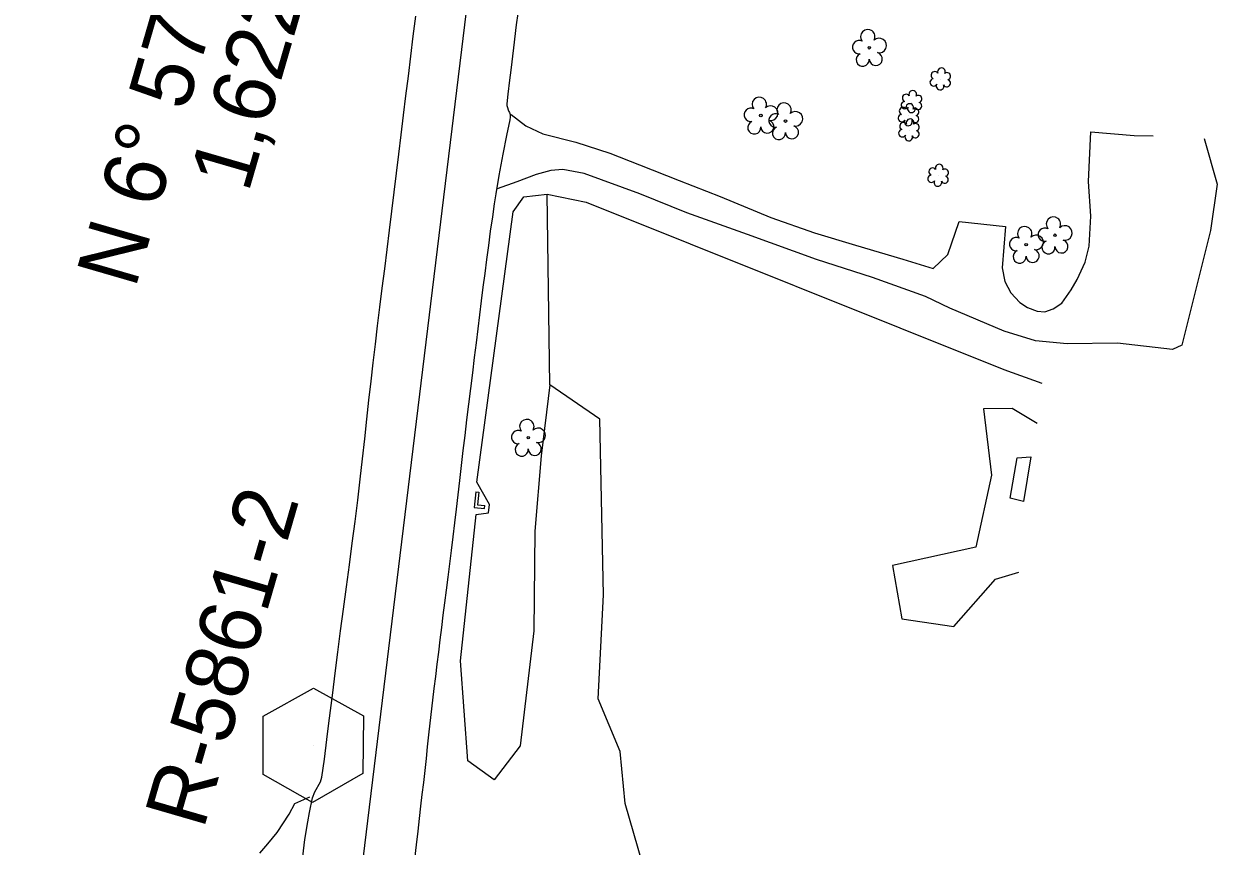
# Model space of a CAD drawing. Extents: x 479429 to 482809, y 488118 to 492379.
# Drawn here: x 481201.3 to 481510.2, y 490268.7 to 490481.6 of the extents above; entities that cross this region are included whole.
import ezdxf

# ---------------------------------------------------------------- set-up
doc = ezdxf.new("R2010")
doc.units = 0
for name, color, linetype in [('CTL Primary Horizontal and Vertical CELL', 7, 'Continuous'), ('CTL Primary Horizontal and Vertical Text', 7, 'Continuous'), ('Exist Horizontal Alignment', 7, 'Continuous'), ('Exist Horizontal Alignment Direction Label', 7, 'Continuous'), ('Exist Other Culture Area Outline', 7, 'Continuous'), ('Exist Roads EOP', 7, 'Continuous'), ('Exist Roads Soil', 7, 'Continuous'), ('Exist Structure Minor Head and End Wall', 7, 'Continuous'), ('Exist Vegetation Hedge Row', 7, 'Continuous'), ('Exist Vegetation Shrub CELL', 7, 'Continuous'), ('Exist Vegetation Tree CELL', 7, 'Continuous'), ('Exist Vegetation Woods Line', 7, 'Continuous')]:
    doc.layers.add(name, color=color, linetype=linetype)

msp = doc.modelspace()

# ---------------------------------------------------------------- linework, layer by layer
at = {"layer": 'CTL Primary Horizontal and Vertical CELL'}
msp.add_line((481276.2, 490294.82), (481276.2, 490294.82), dxfattribs=at)
msp.add_lwpolyline([(481263.27, 490302.31), (481276.27, 490309.56), (481289.27, 490302.41), (481289.07, 490287.51), (481276.07, 490279.96), (481263.27, 490287.21)], close=True, dxfattribs=at)
at = {"layer": 'Exist Horizontal Alignment'}
msp.add_line((481201.31, 489545.89), (481397.95, 491156.7), dxfattribs=at)
at = {"layer": 'Exist Other Culture Area Outline'}
msp.add_lwpolyline([(481462.01, 490369.53), (481460.14, 490357.91), (481456.62, 490358.76), (481458.46, 490369.26), (481462.01, 490369.53)], dxfattribs=at)
at = {"layer": 'Exist Roads EOP'}
for points in [[(481273.37, 490264.51), (481274.03, 490270.38), (481274.8, 490274.93), (481275.25, 490277.39), (481276.03, 490281.18), (481276.68, 490282.73), (481278.07, 490285.35), (481278.31, 490285.97), (481278.46, 490286.53), (481279.11, 490291.18), (481279.77, 490296.33), (481280.21, 490299.8), (481280.72, 490303.81), (481281.28, 490308.38), (481281.92, 490313.5), (481282.6, 490318.93), (481283.31, 490324.46), (481284.05, 490330.08), (481284.81, 490335.79), (481285.58, 490341.51), (481286.32, 490347.16), (481287.04, 490352.75), (481287.73, 490358.27), (481288.38, 490363.7), (481289, 490369), (481289.58, 490374.17), (481290.12, 490379.21), (481290.64, 490384.16), (481291.19, 490389.05), (481291.74, 490393.87), (481292.31, 490398.64), (481292.9, 490403.42), (481293.5, 490408.26), (481294.1, 490413.18), (481294.72, 490418.17), (481295.34, 490423.18), (481295.96, 490428.16), (481296.56, 490433.1), (481297.16, 490438.01), (481297.75, 490442.93), (481298.36, 490447.89), (481298.97, 490452.89), (481299.59, 490457.93), (481300.22, 490463), (481300.85, 490468.11), (481301.49, 490473.25), (481302.13, 490478.41), (481302.77, 490483.61)], [(481329.16, 490484.34), (481328.79, 490481.35), (481328.05, 490475.43), (481327.35, 490469.63), (481327.04, 490467.03), (481326.61, 490463.45), (481326.33, 490460.91), (481326.34, 490460.65), (481326.36, 490460.44), (481326.5, 490459.93), (481326.71, 490459.32), (481326.9, 490458.9), (481327.04, 490458.67), (481327.15, 490458.36), (481327.19, 490458.16), (481327.22, 490457.93), (481327.23, 490457.42), (481327.16, 490456.79), (481326.29, 490452.73), (481325.34, 490447.88), (481324.26, 490442.35), (481323.49, 490437.59), (481323.1, 490434.99), (481322.61, 490431.62), (481322.07, 490427.89), (481321.56, 490424.21), (481321.07, 490420.57), (481320.61, 490416.99), (481320.16, 490413.42), (481319.71, 490409.85), (481319.27, 490406.27), (481318.84, 490402.68), (481318.4, 490399.01), (481317.93, 490395.21), (481317.45, 490391.28), (481316.95, 490387.21), (481316.44, 490383.1), (481315.94, 490379.04), (481315.46, 490375.04), (481314.99, 490371.09), (481314.54, 490367.21), (481314.09, 490363.39), (481313.65, 490359.65), (481313.23, 490355.98), (481312.8, 490352.37), (481312.37, 490348.79), (481311.94, 490345.25), (481311.5, 490341.75), (481311.06, 490338.31), (481310.63, 490334.95), (481310.22, 490331.66), (481309.81, 490328.46), (481309.41, 490325.29), (481309.01, 490322.12), (481308.62, 490318.94), (481308.23, 490315.76), (481307.85, 490312.6), (481307.48, 490309.5), (481307.12, 490306.45), (481306.44, 490300.49), (481306.1, 490297.48), (481305.76, 490294.43), (481305.42, 490291.34), (481305.08, 490288.24), (481304.73, 490285.15), (481304.38, 490282.07), (481304.03, 490279), (481303.66, 490275.85), (481303.27, 490272.51), (481302.86, 490268.99), (481302.43, 490265.28)]]:
    msp.add_lwpolyline(points, dxfattribs=at)
at = {"layer": 'Exist Roads Soil'}
for points in [[(481327.51, 490458.11), (481331.29, 490455.24), (481335.67, 490453.17), (481344.23, 490451.01), (481353, 490448.09), (481360.69, 490445.14), (481370.93, 490441.08), (481381.59, 490436.9), (481394.68, 490431.47), (481406.02, 490427.49), (481416.62, 490424.33), (481428.89, 490420.66), (481436.72, 490418.27), (481440.55, 490421.92), (481443.47, 490430.42), (481455.44, 490429.1), (481454.57, 490418.43), (481455.3, 490414.9), (481456.86, 490411.97), (481459.13, 490409.48), (481461.12, 490408.13), (481463.64, 490407.25), (481465.63, 490407.02), (481467.8, 490407.79), (481470, 490409.32), (481472.47, 490412.7), (481474, 490415.45), (481476.09, 490419.89), (481477.08, 490424.08), (481477.56, 490431.82), (481476.97, 490440.78), (481477.5, 490453.68), (481488.75, 490452.73), (481493.67, 490452.6)], [(481506.89, 490451.91), (481510.24, 490440.06), (481508.48, 490428.08), (481501.06, 490398.42), (481498.72, 490397.25), (481484.43, 490398.92), (481471.41, 490398.74), (481463.22, 490399.51), (481455.09, 490402.02), (481441.03, 490408.02), (481434.75, 490411.02), (481421.03, 490415.89), (481406.48, 490420.61), (481388.65, 490427.04), (481372.96, 490432.66), (481360.8, 490437.59), (481346.39, 490442.84), (481340.87, 490443.86), (481337.73, 490443.63), (481333.95, 490442.59), (481328.94, 490440.73), (481323.87, 490438.9)], [(481262.36, 490266.86), (481264.47, 490269.3), (481266.85, 490272.2), (481269.98, 490276.95), (481271.49, 490279.73), (481275.3, 490281.45)]]:
    msp.add_lwpolyline(points, dxfattribs=at)
at = {"layer": 'Exist Structure Minor Head and End Wall'}
for p, q in [((481318.32, 490360.41), (481319.06, 490360.34)), ((481320.6, 490356.12), (481320.67, 490356.86))]:
    msp.add_line(p, q, dxfattribs=at)
for points in [[(481318.32, 490360.41), (481317.93, 490356.34), (481320.6, 490356.12)], [(481319.06, 490360.34), (481318.75, 490357.02), (481320.67, 490356.86)]]:
    msp.add_lwpolyline(points, dxfattribs=at)
at = {"layer": 'Exist Vegetation Hedge Row'}
msp.add_lwpolyline([(481337.45, 490388.16), (481335.27, 490369.72), (481333.58, 490350.26), (481333.32, 490324.41), (481329.78, 490294.62), (481323.06, 490285.85), (481316.25, 490290.78), (481314.34, 490316.65), (481318.44, 490354.56), (481321.57, 490354.98), (481321.87, 490357.17), (481318.62, 490362.95), (481328.02, 490432.9), (481330.71, 490436.79), (481336.76, 490437.47)], dxfattribs=at)
at = {"layer": 'Exist Vegetation Shrub CELL'}
for p, q in [((481438.64, 490467.18), (481438.64, 490467.18)), ((481431.2, 490461.3), (481431.2, 490461.3)), ((481430.41, 490457.9), (481430.41, 490457.9)), ((481430.53, 490453.98), (481430.53, 490453.98)), ((481438.07, 490442.22), (481438.07, 490442.22))]:
    msp.add_line(p, q, dxfattribs=at)
for centre, radius, start, end in [((481436.84, 490466.47), 0.955, 95.1099, 327.9534), ((481437.16, 490468.3), 0.968, 35.8908, 245.4216), ((481438.87, 490469.22), 0.99, 334.8391, 200.4717), ((481440.31, 490468.05), 0.929, 284.4567, 126.0861), ((481431.43, 490463.34), 0.99, 334.8391, 200.4717), ((481438.51, 490465.49), 0.984, 151.2797, 21.387), ((481440.28, 490466.25), 0.937, 204.9913, 73.4601), ((481429.4, 490460.59), 0.955, 95.1099, 327.9534), ((481429.72, 490462.42), 0.968, 35.8908, 245.4216), ((481432.84, 490460.37), 0.937, 204.9913, 73.4601), ((481432.88, 490462.17), 0.929, 284.4567, 126.0861), ((481428.61, 490457.19), 0.955, 95.1099, 327.9534), ((481428.92, 490459.03), 0.968, 35.8908, 245.4216), ((481430.64, 490459.94), 0.99, 334.8391, 200.4717), ((481431.08, 490459.61), 0.984, 151.2797, 21.387), ((481432.08, 490458.77), 0.929, 284.4567, 126.0861), ((481429.05, 490455.11), 0.968, 35.8908, 245.4216), ((481430.28, 490456.22), 0.984, 151.2797, 21.387), ((481430.76, 490456.02), 0.99, 334.8391, 200.4717), ((481432.04, 490456.97), 0.937, 204.9913, 73.4601), ((481432.2, 490454.85), 0.929, 284.4567, 126.0861), ((481428.73, 490453.28), 0.955, 95.1099, 327.9534), ((481430.4, 490452.3), 0.984, 151.2797, 21.387), ((481432.17, 490453.05), 0.937, 204.9913, 73.4601), ((481436.58, 490443.34), 0.968, 35.8908, 245.4216), ((481438.29, 490444.26), 0.99, 334.8391, 200.4717), ((481439.74, 490443.08), 0.929, 284.4567, 126.0861), ((481436.27, 490441.51), 0.955, 95.1099, 327.9534), ((481437.94, 490440.53), 0.984, 151.2797, 21.387), ((481439.7, 490441.29), 0.937, 204.9913, 73.4601)]:
    msp.add_arc(centre, radius, start, end, dxfattribs=at)
at = {"layer": 'Exist Vegetation Tree CELL'}
for p, q in [((481420.18, 490475.43), (481420.18, 490475.43)), ((481392.1, 490457.89), (481392.1, 490457.89)), ((481398.49, 490456.44), (481398.49, 490456.44)), ((481460.81, 490424.43), (481460.81, 490424.43)), ((481468.26, 490426.88), (481468.26, 490426.88)), ((481331.9, 490374.46), (481331.9, 490374.46))]:
    msp.add_line(p, q, dxfattribs=at)
for centre in [(481420.18, 490475.43), (481392.1, 490457.89), (481398.49, 490456.44), (481468.26, 490426.88), (481460.81, 490424.43), (481331.9, 490374.46)]:
    msp.add_circle(centre, 0.326, dxfattribs=at)
for centre, radius, start, end in [((481419.8, 490478.3), 1.86, 330.1651, 219.7134), ((481417.58, 490475.58), 1.73, 62.6636, 279.3457), ((481422.73, 490476.01), 1.9, 257.1011, 134.1999), ((481418.48, 490472.31), 1.69, 111.5671, 6.231), ((481421.86, 490472.53), 1.7, 181.2822, 74.56), ((481391.71, 490460.76), 1.86, 330.1651, 219.7134), ((481398.1, 490459.32), 1.86, 330.1651, 219.7134), ((481389.49, 490458.04), 1.73, 62.6636, 279.3457), ((481394.65, 490458.48), 1.9, 257.1011, 134.1999), ((481395.88, 490456.6), 1.73, 62.6636, 279.3457), ((481401.04, 490457.03), 1.9, 257.1011, 134.1999), ((481390.39, 490454.77), 1.69, 111.5671, 6.231), ((481393.77, 490454.99), 1.7, 181.2822, 74.56), ((481400.16, 490453.54), 1.7, 181.2822, 74.56), ((481396.78, 490453.32), 1.69, 111.5671, 6.231), ((481467.87, 490429.75), 1.86, 330.1651, 219.7134), ((481460.42, 490427.3), 1.86, 330.1651, 219.7134), ((481465.65, 490427.03), 1.73, 62.6636, 279.3457), ((481470.81, 490427.46), 1.9, 257.1011, 134.1999), ((481458.2, 490424.58), 1.73, 62.6636, 279.3457), ((481463.35, 490425.02), 1.9, 257.1011, 134.1999), ((481466.56, 490423.76), 1.69, 111.5671, 6.231), ((481469.93, 490423.98), 1.7, 181.2822, 74.56), ((481459.1, 490421.31), 1.69, 111.5671, 6.231), ((481462.48, 490421.53), 1.7, 181.2822, 74.56), ((481331.52, 490377.33), 1.86, 330.1651, 219.7134), ((481329.3, 490374.61), 1.73, 62.6636, 279.3457), ((481334.45, 490375.05), 1.9, 257.1011, 134.1999), ((481330.2, 490371.34), 1.69, 111.5671, 6.231), ((481333.58, 490371.56), 1.7, 181.2822, 74.56)]:
    msp.add_arc(centre, radius, start, end, dxfattribs=at)
at = {"layer": 'Exist Vegetation Woods Line'}
for points in [[(481336.76, 490437.47), (481346.91, 490435.42), (481455.03, 490392.14), (481464.88, 490388.54)], [(481355.7, 490293.17), (481349.96, 490306.84), (481351.33, 490333.74), (481350.46, 490379.28), (481337.45, 490388.16), (481336.76, 490437.47)], [(481463.61, 490378.09), (481457.2, 490382.04), (481449.71, 490381.96), (481451.83, 490364.78), (481447.8, 490346.08), (481426.19, 490341.39), (481428.58, 490327.58), (481442.09, 490325.55), (481452.82, 490337.85), (481458.91, 490339.62)], [(481427.35, 490081.24), (481394.6, 490076.17), (481381.34, 490139.35), (481356.08, 490180.77), (481357.25, 490231.7), (481366.21, 490244.77), (481361.43, 490264.2), (481356.94, 490279.7), (481355.7, 490293.17)]]:
    msp.add_lwpolyline(points, dxfattribs=at)

# ---------------------------------------------------------------- texts
at = {"layer": 'CTL Primary Horizontal and Vertical Text'}
msp.add_text('R-5861-2', height=16, rotation=73.8069, dxfattribs=at).set_placement((481247.79, 490272.74))
at = {"layer": 'Exist Horizontal Alignment Direction Label'}
for s, p in [('N 6%%d 57\' 37" E', (481230.12, 490412.81)), ('1,622.77', (481259.4, 490437.61))]:
    msp.add_text(s, height=16, rotation=73.8069, dxfattribs=at).set_placement(p)

doc.saveas('drawing.dxf')
